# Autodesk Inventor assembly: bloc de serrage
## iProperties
Shininess: 64.0
Length Units: 11269
Angle Units: 11279
Time Units: 11290
Mass Units: 11283
Length Display Precision: 3
Angle Display Precision: 2
Compacted: True
Created: 2004-12
Part Number: bloc de serrage
Document SubType Name: Assembly
Designer: LEGERET Philippe
Density: 0.0
Volumn: 0.0
Area: 0.0
PropertySet Name: Model Information
Control State: 0
Master: False
Checked Out: False
Author: LEGERET Philippe
